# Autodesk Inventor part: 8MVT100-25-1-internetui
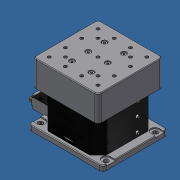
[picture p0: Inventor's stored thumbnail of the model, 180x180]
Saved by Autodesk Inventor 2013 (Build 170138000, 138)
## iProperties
Created: 2013-06
Part Number: 8MVT100-25-1-internetui
Material: Generic
Document SubType Name: Modeling
Designer: Darius.M
Density: 1 g/cm^3
Author: Darius.M
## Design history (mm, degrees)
derived "8MVT100-25-1.iam"
body "Solid1"
node "8MVT100-25.10.ipt:1"
node "8MVT100-25.16.ipt:1"
node "8MVT100-25.12-01.ipt:1"
node "8MVT100-25.19.ipt:1"
node "DIN 912  - replaced by DIN EN ISO 4762 M2.5 x 6:1"
node "DIN 912  - replaced by DIN EN ISO 4762 M2.5 x 6:2"
node "DIN 912  - replaced by DIN EN ISO 4762 M2.5 x 6:3"
node "DIN 912  - replaced by DIN EN ISO 4762 M2.5 x 6:4"
node "DIN 912  - replaced by DIN EN ISO 4762 M2.5 x 6:5"
node "DIN 912  - replaced by DIN EN ISO 4762 M2.5 x 6:6"
node "DIN 912 - replaced by DIN EN ISO 4762 M4 x 12:1"
node "DIN 912 - replaced by DIN EN ISO 4762 M4 x 12:2"
node "DIN 912 - replaced by DIN EN ISO 4762 M4 x 12:3"
node "DIN 912 - replaced by DIN EN ISO 4762 M4 x 12:5"
node "DIN 912 - replaced by DIN EN ISO 4762 M4 x 12:6"
node "DIN 912 - replaced by DIN EN ISO 4762 M4 x 12:7"
node "DIN 912 - replaced by DIN EN ISO 4762 M4 x 12:8"
node "DIN 912 - replaced by DIN EN ISO 4762 M4 x 12:9"
node "DIN 912 - replaced by DIN EN ISO 4762 M4 x 12:10"
node "DIN 912 - replaced by DIN EN ISO 4762 M4 x 12:11"
node "DIN 912 - replaced by DIN EN ISO 4762 M4 x 12:12"
node "varztas DB jungtims.ipt:1"
node "varztas DB jungtims.ipt:2"
node "kabelinis kistukasDB9(M).ipt:1"
node "8MVT100-25.11-01.ipt:1"
node "DIN 912 - replaced by DIN EN ISO 4762 M4 x 12:13"
node "8MVT100-25.01-01.ipt:1"
node "8MVT70-13.17.ipt:1"
node "8MVT70-13.14.ipt:1"
node "DIN 912  - replaced by DIN EN ISO 4762 M2.5 x 6:7"
node "DIN 912  - replaced by DIN EN ISO 4762 M2.5 x 6:8"
node "DIN 912  - replaced by DIN EN ISO 4762 M2.5 x 12:1"
node "DIN 912  - replaced by DIN EN ISO 4762 M2.5 x 12:2"
node "8MVT100-25-1.iam_Bodies"
